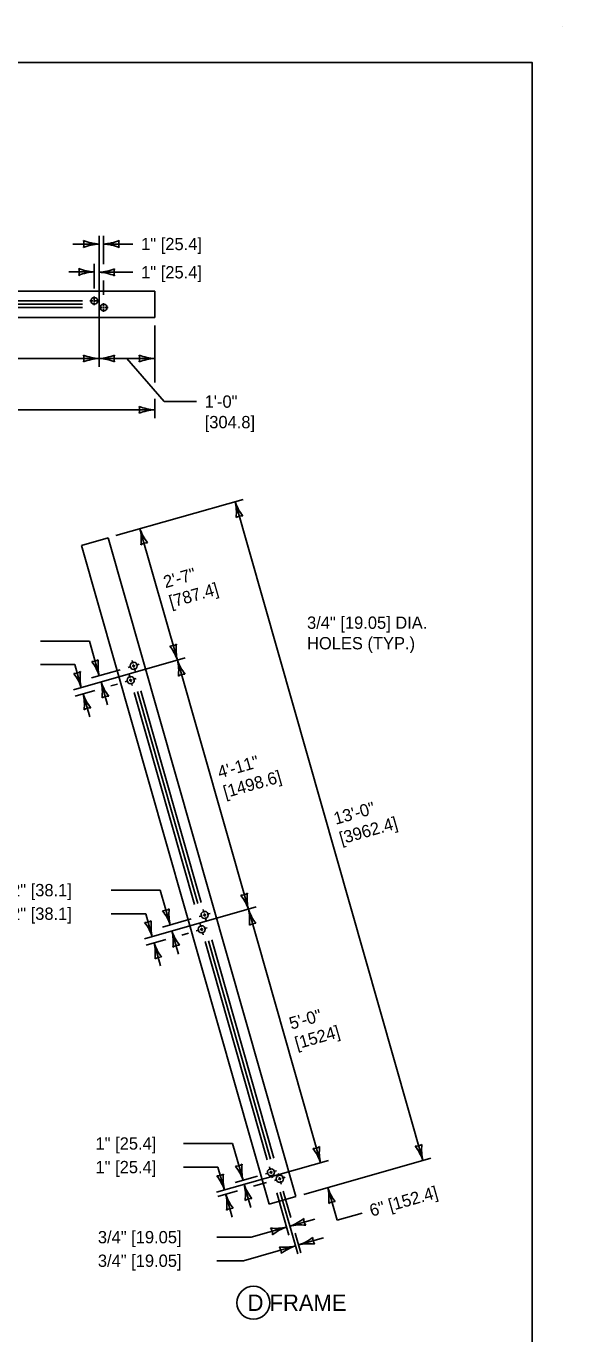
# Model space of a CAD drawing. Extents: x 49991.4 to 50021, y 49987.6 to 50011.4.
# Drawn here: x 50014.29 to 50016.9, y 49992.81 to 49999.18 of the extents above; entities that cross this region are included whole.
import ezdxf

# ---------------------------------------------------------------- set-up
doc = ezdxf.new("R2010")
doc.units = 0
for name, color, linetype in [('Level 1', 7, 'Continuous'), ('Level 2', 7, 'Continuous'), ('Level 3', 7, 'Continuous'), ('Level 5', 7, 'Continuous')]:
    doc.layers.add(name, color=color, linetype=linetype)

msp = doc.modelspace()

# ---------------------------------------------------------------- linework, layer by layer
at = {"layer": 'Level 1'}
for p, q in [((50016.9001, 49999.1756), (50016.9001, 49999.1756)), ((50011.6513, 49997.8849), (50014.9124, 49997.8849)), ((50014.9124, 49997.8849), (50014.9124, 49997.7571)), ((50014.5603, 49997.8371), (50013.3735, 49997.8371)), ((50013.3735, 49997.8211), (50014.5603, 49997.8211)), ((50014.5603, 49997.8051), (50013.3735, 49997.8051)), ((50011.6513, 49997.7571), (50014.9124, 49997.7571)), ((50014.5549, 49996.6457), (50014.6849, 49996.6828)), ((50015.4693, 49993.437), (50014.5549, 49996.6457)), ((50015.5995, 49993.4741), (50014.6849, 49996.6828)), ((50015.1386, 49994.9064), (50014.8443, 49995.9387)), ((50015.1059, 49994.8971), (50014.8117, 49995.9294)), ((50015.1222, 49994.9017), (50014.8282, 49995.9341)), ((50015.4606, 49993.6527), (50015.1575, 49994.7161)), ((50015.4768, 49993.6573), (50015.1738, 49994.7208)), ((50015.4931, 49993.6619), (50015.1901, 49994.7254)), ((50015.5995, 49993.4741), (50015.4693, 49993.437))]:
    msp.add_line(p, q, dxfattribs=at)
msp.add_lwpolyline([(49999.3835, 49998.9992), (50016.7501, 49998.9992), (50016.7501, 49987.7988), (49999.3835, 49987.7988)], close=True, dxfattribs=at)
for centre in [(50014.8095, 49996.0596), (50014.7952, 49995.9898), (50015.1551, 49994.8462), (50015.1408, 49994.7763), (50015.4782, 49993.5925), (50015.5214, 49993.5609)]:
    msp.add_circle(centre, 0.0175, dxfattribs=at)
for centre in [(50014.618, 49997.837), (50014.6633, 49997.8051)]:
    msp.add_ellipse(centre, major_axis=(0.017, 0), ratio=0.940299, dxfattribs=at)
at = {"layer": 'Level 2'}
msp.add_circle((50015.3927, 49992.9573), 0.08, dxfattribs=at)
at = {"layer": 'Level 3'}
for p, q in [((50014.5134, 49998.1144), (50014.6407, 49998.1144)), ((50014.6407, 49997.8939), (50014.6407, 49998.1544)), ((50014.6633, 49998.0167), (50014.6633, 49998.1544)), ((50014.6633, 49998.1144), (50014.8061, 49998.1144)), ((50014.4939, 49997.9785), (50014.6179, 49997.9785)), ((50014.6179, 49997.8983), (50014.6179, 49998.0185)), ((50014.6407, 49997.9767), (50014.8061, 49997.9767)), ((50014.6633, 49997.8664), (50014.6633, 49997.9367)), ((50014.6179, 49997.8983), (50014.6179, 49997.904)), ((50014.6407, 49997.698), (50014.6407, 49997.9005)), ((50014.6407, 49997.738), (50014.6407, 49997.5168)), ((50014.9124, 49997.7171), (50014.9124, 49997.4399)), ((50013.2819, 49997.5568), (50014.6407, 49997.5568)), ((50014.6407, 49997.5568), (50014.9124, 49997.5568)), ((50014.9124, 49997.3599), (50014.9124, 49997.2668)), ((50011.6513, 49997.3068), (50014.9124, 49997.3068)), ((50015.3422, 49996.8705), (50014.7234, 49996.6938)), ((50016.2183, 49993.6507), (50015.3037, 49996.8595)), ((50015.0226, 49996.0874), (50014.8403, 49996.7272)), ((50014.5937, 49996.1806), (50014.3551, 49996.1806)), ((50014.6421, 49996.0116), (50014.5937, 49996.1806)), ((50014.5226, 49996.0658), (50014.3551, 49996.0658)), ((50015.0611, 49996.0984), (50014.5161, 49995.9428)), ((50014.5546, 49995.9538), (50014.5226, 49996.0658)), ((50015.3684, 49994.874), (50015.0226, 49996.0874)), ((50014.7446, 49996.0408), (50014.6036, 49996.0007)), ((50014.6211, 49995.9399), (50014.5248, 49995.9124)), ((50014.6829, 49995.869), (50014.6508, 49995.9812)), ((50014.7303, 49995.971), (50014.698, 49995.9618)), ((50014.5954, 49995.8112), (50014.5633, 49995.9234)), ((50014.9393, 49994.9672), (50014.7007, 49994.9672)), ((50014.9877, 49994.7982), (50014.9393, 49994.9672)), ((50015.4069, 49994.885), (50014.8617, 49994.7294)), ((50015.7201, 49993.6398), (50015.3684, 49994.874)), ((50014.8682, 49994.8524), (50014.7007, 49994.8524)), ((50014.9002, 49994.7404), (50014.8682, 49994.8524)), ((50015.0902, 49994.8274), (50014.9492, 49994.7873)), ((50014.9667, 49994.7265), (50014.8704, 49994.699)), ((50015.0282, 49994.6557), (50014.9961, 49994.7677)), ((50015.0759, 49994.7577), (50015.0436, 49994.7484)), ((50014.941, 49994.5978), (50014.9089, 49994.71)), ((50015.291, 49993.733), (50015.0524, 49993.733)), ((50015.3423, 49993.554), (50015.291, 49993.733)), ((50015.7586, 49993.6508), (50015.2134, 49993.4952)), ((50016.2568, 49993.6617), (50015.638, 49993.4851)), ((50015.2199, 49993.6182), (50015.0524, 49993.6182)), ((50015.2519, 49993.5062), (50015.2199, 49993.6182)), ((50015.4131, 49993.5742), (50015.3038, 49993.5431)), ((50015.3799, 49993.4215), (50015.3478, 49993.5335)), ((50015.4564, 49993.5425), (50015.3925, 49993.5243)), ((50015.8002, 49993.3592), (50015.7547, 49993.5184)), ((50015.3156, 49993.5024), (50015.2192, 49993.4749)), ((50015.2898, 49993.3737), (50015.2577, 49993.4859)), ((50015.5652, 49993.2872), (50015.5068, 49993.4919)), ((50015.6084, 49993.1956), (50015.5226, 49993.4964)), ((50015.5749, 49993.3732), (50015.5385, 49993.5009)), ((50015.9219, 49993.3939), (50015.8002, 49993.3592)), ((50015.5542, 49993.3257), (50015.3827, 49993.2767)), ((50015.6917, 49993.3649), (50015.57, 49993.3302)), ((50015.3827, 49993.2767), (50015.2152, 49993.2767)), ((50015.6241, 49993.2001), (50015.5968, 49993.2963)), ((50015.7348, 49993.2733), (50015.6132, 49993.2386)), ((50015.5974, 49993.2341), (50015.3448, 49993.1619)), ((50015.3448, 49993.1619), (50015.2152, 49993.1619))]:
    msp.add_line(p, q, dxfattribs=at)
msp.add_lwpolyline([(50014.7766, 49997.5568), (50014.9583, 49997.3469), (50015.1155, 49997.3469)], dxfattribs=at)
for centre, radius, start, end in [((50014.6499, 49998.3365), 0.2223, 247.45601, 267.63952), ((50014.5125, 49998.1144), 0.0548, 342.13882, 17.86118), ((50014.6522, 49997.8817), 0.233, 92.82731, 112.07716), ((50014.6518, 49998.3471), 0.233, 272.82731, 292.07716), ((50014.6541, 49997.8923), 0.2223, 67.45601, 87.63952), ((50014.7915, 49998.1144), 0.0548, 162.13882, 197.86118), ((50014.6271, 49998.2006), 0.2223, 247.45601, 267.63952), ((50014.4897, 49997.9785), 0.0548, 342.13882, 17.86118), ((50014.6294, 49997.7458), 0.233, 92.82731, 112.07716), ((50014.6292, 49998.2094), 0.233, 272.82731, 292.07716), ((50014.6315, 49997.7546), 0.2223, 67.45601, 87.63952), ((50014.7689, 49997.9767), 0.0548, 162.13882, 197.86118), ((50014.6499, 49997.7789), 0.2223, 247.45601, 267.63952), ((50014.5125, 49997.5568), 0.0548, 342.13882, 17.86118), ((50014.6522, 49997.3241), 0.233, 92.82731, 112.07716), ((50014.6292, 49997.7895), 0.233, 272.82731, 292.07716), ((50014.6315, 49997.3347), 0.2223, 67.45601, 87.63952), ((50014.7689, 49997.5568), 0.0548, 162.13882, 197.86118), ((50014.9216, 49997.7789), 0.2223, 247.45601, 267.63952), ((50014.7842, 49997.5568), 0.0548, 342.13882, 17.86118), ((50014.9239, 49997.3241), 0.233, 92.82731, 112.07716), ((50014.9216, 49997.5289), 0.2223, 247.45601, 267.63952), ((50014.7842, 49997.3068), 0.0548, 342.13882, 17.86118), ((50014.9239, 49997.0741), 0.233, 92.82731, 112.07716), ((50015.0876, 49996.8074), 0.2223, 353.36508, 13.54859), ((50015.5243, 49996.9343), 0.233, 198.73638, 217.98623), ((50015.3388, 49996.7362), 0.0548, 88.04789, 123.77025), ((50014.6242, 49996.6751), 0.2223, 353.36, 13.54351), ((50015.061, 49996.802), 0.233, 198.7313, 217.98115), ((50014.8754, 49996.6039), 0.0548, 88.04281, 123.76517), ((50014.9875, 49996.2107), 0.0548, 268.04281, 303.76517), ((50014.8019, 49996.0126), 0.233, 18.7313, 37.98115), ((50015.2387, 49996.1394), 0.2223, 173.36, 193.54351), ((50014.6069, 49996.1349), 0.0548, 268.08575, 303.80811), ((50014.4215, 49995.9366), 0.233, 18.77424, 38.02409), ((50014.8582, 49996.0639), 0.2223, 173.40294, 193.58645), ((50014.8065, 49996.0353), 0.2223, 353.36273, 13.54624), ((50015.2433, 49996.1622), 0.233, 198.73403, 217.98388), ((50014.5194, 49996.077), 0.0548, 268.09279, 303.81515), ((50014.334, 49995.8788), 0.233, 18.78128, 38.03113), ((50014.7707, 49996.006), 0.2223, 173.40998, 193.59349), ((50015.0577, 49995.9641), 0.0548, 88.04554, 123.7679), ((50014.4347, 49995.929), 0.2223, 353.4033, 13.58681), ((50014.8714, 49996.0562), 0.233, 198.7746, 218.02445), ((50014.3472, 49995.8712), 0.2223, 353.40294, 13.58645), ((50014.7839, 49995.9984), 0.233, 198.77424, 218.02409), ((50014.686, 49995.8579), 0.0548, 88.08611, 123.80847), ((50014.5985, 49995.8001), 0.0548, 88.08575, 123.80811), ((50015.3333, 49994.9973), 0.0548, 268.04554, 303.7679), ((50015.1477, 49994.7992), 0.233, 18.73403, 37.98388), ((50015.5845, 49994.9261), 0.2223, 173.36273, 193.54624), ((50014.9525, 49994.9215), 0.0548, 268.08575, 303.80811), ((50014.7671, 49994.7232), 0.233, 18.77424, 38.02409), ((50015.2038, 49994.8505), 0.2223, 173.40294, 193.58645), ((50015.1523, 49994.8219), 0.2223, 353.36154, 13.54505), ((50015.5891, 49994.9488), 0.233, 198.73284, 217.98269), ((50014.865, 49994.8636), 0.0548, 268.09279, 303.81515), ((50014.6796, 49994.6653), 0.233, 18.78128, 38.03113), ((50015.1163, 49994.7926), 0.2223, 173.40998, 193.59349), ((50015.4035, 49994.7507), 0.0548, 88.04435, 123.76671), ((50014.78, 49994.7155), 0.2223, 353.4033, 13.58681), ((50015.2167, 49994.8427), 0.233, 198.7746, 218.02445), ((50014.6928, 49994.6578), 0.2223, 353.40294, 13.58645), ((50015.1295, 49994.785), 0.233, 198.77424, 218.02409), ((50015.0314, 49994.6445), 0.0548, 88.08611, 123.80847), ((50014.9441, 49994.5867), 0.0548, 88.08575, 123.80811), ((50015.685, 49993.7631), 0.0548, 268.04435, 303.76671), ((50015.4994, 49993.565), 0.233, 18.73284, 37.98269), ((50015.9362, 49993.6919), 0.2223, 173.36154, 193.54505), ((50016.1832, 49993.774), 0.0548, 268.04789, 303.77025), ((50015.9976, 49993.5759), 0.233, 18.73638, 37.98623), ((50016.4344, 49993.7028), 0.2223, 173.36508, 193.54859), ((50015.2167, 49993.6294), 0.0548, 268.09279, 303.81515), ((50015.468, 49993.5584), 0.2223, 173.40998, 193.59349), ((50015.3071, 49993.6773), 0.0548, 268.08575, 303.80811), ((50015.1217, 49993.479), 0.233, 18.77424, 38.02409), ((50015.5584, 49993.6063), 0.2223, 173.40294, 193.58645), ((50015.0313, 49993.4311), 0.233, 18.78128, 38.03113), ((50015.1317, 49993.4813), 0.2223, 353.4033, 13.58681), ((50015.5684, 49993.6085), 0.233, 198.7746, 218.02445), ((50015.5386, 49993.4662), 0.2223, 353.40616, 13.58967), ((50015.9753, 49993.5934), 0.233, 198.77746, 218.02731), ((50015.0416, 49993.4336), 0.2223, 353.40294, 13.58645), ((50015.4783, 49993.5609), 0.233, 198.77424, 218.02409), ((50015.3831, 49993.4103), 0.0548, 88.08611, 123.80847), ((50015.2929, 49993.3626), 0.0548, 88.08575, 123.80811), ((50015.7899, 49993.3951), 0.0548, 88.08897, 123.81133), ((50015.502, 49993.5418), 0.2223, 263.39428, 283.57778), ((50015.6292, 49993.1051), 0.233, 108.76558, 128.01543), ((50015.4952, 49993.5509), 0.233, 288.72532, 307.97517), ((50015.6221, 49993.1141), 0.2223, 83.35403, 103.53753), ((50015.6933, 49993.3653), 0.0548, 178.03683, 213.75919), ((50015.431, 49993.2905), 0.0548, 358.07708, 33.79944), ((50015.5384, 49993.4593), 0.233, 288.72532, 307.97517), ((50015.7365, 49993.2737), 0.0548, 178.03683, 213.75919), ((50015.5452, 49993.4502), 0.2223, 263.40141, 283.58492), ((50015.4742, 49993.1989), 0.0548, 358.08422, 33.80658), ((50015.6724, 49993.0135), 0.233, 108.77271, 128.02256), ((50015.6652, 49993.0225), 0.2223, 83.35403, 103.53753)]:
    msp.add_arc(centre, radius, start, end, dxfattribs=at)
at = {"layer": 'Level 5'}
for p, q in [((50014.6179, 49997.8583), (50014.6179, 49997.8445)), ((50014.5953, 49997.8371), (50014.61, 49997.8371)), ((50014.6136, 49997.8371), (50014.6229, 49997.8371)), ((50014.6179, 49997.842), (50014.6179, 49997.8328)), ((50014.6179, 49997.8295), (50014.6179, 49997.8158)), ((50014.6259, 49997.8371), (50014.6407, 49997.8371)), ((50014.6407, 49997.8051), (50014.6554, 49997.8051)), ((50014.6589, 49997.8051), (50014.6682, 49997.8051)), ((50014.6633, 49997.8264), (50014.6633, 49997.8125)), ((50014.6633, 49997.81), (50014.6633, 49997.8009)), ((50014.6633, 49997.7977), (50014.6633, 49997.7838)), ((50014.6712, 49997.8051), (50014.6859, 49997.8051)), ((50014.8019, 49996.086), (50014.806, 49996.0715)), ((50014.8074, 49996.0667), (50014.8116, 49996.0523)), ((50014.8359, 49996.0672), (50014.8215, 49996.0631)), ((50014.7974, 49996.0561), (50014.783, 49996.0519)), ((50014.7876, 49996.0162), (50014.7918, 49996.0017)), ((50014.8166, 49996.0617), (50014.8022, 49996.0575)), ((50014.813, 49996.0475), (50014.8171, 49996.0331)), ((50014.7832, 49995.9863), (50014.7687, 49995.9821)), ((50014.8024, 49995.9918), (50014.788, 49995.9877)), ((50014.7932, 49995.9969), (50014.7974, 49995.9824)), ((50014.7987, 49995.9776), (50014.8028, 49995.9632)), ((50014.8217, 49995.9973), (50014.8073, 49995.9932)), ((50015.1475, 49994.8725), (50015.1516, 49994.8581)), ((50015.153, 49994.8533), (50015.1572, 49994.8388)), ((50015.1816, 49994.8537), (50015.1672, 49994.8496)), ((50015.143, 49994.8426), (50015.1286, 49994.8385)), ((50015.1332, 49994.8027), (50015.1374, 49994.7882)), ((50015.1623, 49994.8482), (50015.1479, 49994.8441)), ((50015.1586, 49994.834), (50015.1627, 49994.8196)), ((50015.1288, 49994.7728), (50015.1144, 49994.7686)), ((50015.148, 49994.7783), (50015.1336, 49994.7742)), ((50015.1388, 49994.7834), (50015.143, 49994.769)), ((50015.1443, 49994.7641), (50015.1484, 49994.7498)), ((50015.1673, 49994.7838), (50015.1529, 49994.7797)), ((50015.4661, 49993.5892), (50015.4516, 49993.5851)), ((50015.4747, 49993.6047), (50015.4706, 49993.6191)), ((50015.4853, 49993.5947), (50015.4709, 49993.5906)), ((50015.4802, 49993.5854), (50015.4761, 49993.5999)), ((50015.4856, 49993.5661), (50015.4815, 49993.5806)), ((50015.5046, 49993.6002), (50015.4902, 49993.5961)), ((50015.5179, 49993.5731), (50015.5138, 49993.5875)), ((50015.5093, 49993.5576), (50015.4949, 49993.5535)), ((50015.5286, 49993.563), (50015.5142, 49993.5589)), ((50015.5233, 49993.5538), (50015.5193, 49993.5683)), ((50015.5288, 49993.5345), (50015.5247, 49993.549)), ((50015.5479, 49993.5685), (50015.5335, 49993.5644))]:
    msp.add_line(p, q, dxfattribs=at)

# ---------------------------------------------------------------- texts
at = {"layer": 'Level 2'}
for s, height, p in [('1" [25.4]', 0.06, (50014.8461, 49998.0844)), ('1" [25.4]', 0.06, (50014.8461, 49997.9467)), ('1\'-0"', 0.06, (50015.1555, 49997.3169)), ('[304.8]', 0.06, (50015.1555, 49997.2169)), ('3/4" [19.05] DIA.', 0.06, (50015.6541, 49996.2399)), ('HOLES (TYP.)', 0.06, (50015.6541, 49996.1399)), ('1 1/2" [38.1]', 0.06, (50014.0786, 49994.9372)), ('1 1/2" [38.1]', 0.06, (50014.0786, 49994.8224)), ('1" [25.4]', 0.06, (50014.6238, 49993.703)), ('1" [25.4]', 0.06, (50014.6238, 49993.5882)), ('3/4" [19.05]', 0.06, (50014.6352, 49993.2467)), ('3/4" [19.05]', 0.06, (50014.6352, 49993.1319)), ('D FRAME', 0.08, (50015.3646, 49992.9173))]:
    msp.add_text(s, height=height, dxfattribs=at).set_placement(p)
for s, p in [('2\'-7"', (50014.9644, 49996.4375)), ('[787.4]', (50014.9918, 49996.3413)), ('4\'-11"', (50015.2285, 49995.5109)), ('[1498.6]', (50015.2559, 49995.4147)), ('13\'-0"', (50015.794, 49995.2853)), ('[3962.4]', (50015.8214, 49995.1891)), ('5\'-0"', (50015.5772, 49994.2871)), ('[1524]', (50015.6046, 49994.1909)), ('6" [152.4]', (50015.9686, 49993.376))]:
    msp.add_text(s, height=0.06, rotation=15.90553, dxfattribs=at).set_placement(p)

doc.saveas('drawing.dxf')
